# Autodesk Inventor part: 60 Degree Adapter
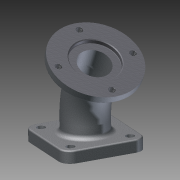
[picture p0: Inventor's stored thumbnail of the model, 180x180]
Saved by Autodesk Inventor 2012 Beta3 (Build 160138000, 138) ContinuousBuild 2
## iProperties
Created: 2010-11
Part Number: 60 Degree Adapter
Material: Default
Document SubType Name: Modeling
Designer: Beta-8540w
Density: 1 g/cm^3
Author: Beta-8540w
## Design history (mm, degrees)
sketch "Sketch1"
  geometry: L1 (50, 50)-(50, -50); L2 (50, -50)-(-50, -50); L3 (-50, -50)-(-50, 50); L4 (-50, 50)-(50, 50); C1 r 28 at (0, 0); C2 r 20 at (0, 0); 2 further points
  constraints: 8 end point, 3 coincident, 2 centre point, 1 horizontal, 9 other
  dimensions: "d0" = 100 distance of L3.end L1.start; "d8" = 8 radial gap between concentric circles of C1 C2; "d17" = 40 diameter of C2
extrude "Extrusion1" new body sketch "Sketch1" distance "d1" = 15; taper "d2" = 0 deg
sketch "Sketch2"
  geometry: L1 (0, 0)-(0, 30); L2 (-13.397, 80)-(-28.397, 105.981); A1 r 100 centre (-100, 30) between (0, 30) and (-13.397, 80)
  constraints: 4 end point, 2 point on circle, 2 tangent, 1 centre point, 1 vertical
  dimensions: "d3" = 30 distance of L1.start L1.end; "d4" = 30 distance of L2.start L2.end; "d5" = 150 deg angle of L1 L2; "d6" = 100 radius of A1
workplane "Work Plane1"
sketch "Sketch3"
  geometry: C1 r 55 at (0, 0); 2 further points
  constraints: 1 centre point, 1 coincident
  dimensions: "d9" = 110 diameter of C1
extrude "Extrusion2" join sketch "Sketch3" distance "d10" = 10; taper "d11" = 0 deg
sweep "Sweep1" dims "d12" = 0
sweep "Sweep2" dims "d13" = 0
fillet "Fillet1" dims "d14" = 14, "d15" = 6, "d16" = 2
hole "Hole1" diameter "d20" = 11; stored, may be unused: countersink angle "d24" = 90 deg, drill point angle "d26" = 118 deg; dims "d18" = 10, "d19" = 10, "d21" = 6, "d22" = 20, "d23" = 2, "d25" = 8
hole "Hole2" diameter "d29" = 11; stored, may be unused: countersink angle "d33" = 90 deg, drill point angle "d35" = 118 deg; dims "d27" = 10, "d28" = 10, "d30" = 6, "d31" = 20, "d32" = 2, "d34" = 8
hole "Hole3" diameter "d38" = 11; stored, may be unused: countersink angle "d42" = 90 deg, drill point angle "d44" = 118 deg; dims "d36" = 10, "d37" = 10, "d39" = 6, "d40" = 20, "d41" = 2, "d43" = 8
hole "Hole4" diameter "d47" = 11; stored, may be unused: countersink angle "d51" = 90 deg, drill point angle "d53" = 118 deg; dims "d45" = 10, "d46" = 10, "d48" = 6, "d49" = 20, "d50" = 2, "d52" = 8
sketch "Sketch4" dims "d54" = 90
  geometry: L1 (0, 45)-(45, 0); L2 (45, 0)-(0, -45); L3 (0, -45)-(-45, 0); L4 (-45, 0)-(0, 45); C1 r 55 at (0, 0) reference; 3 further points
  constraints: 8 end point, 2 coincident, 1 vertical alignment, 11 other
hole "Hole5" sketch "Sketch4" at (0, 45), (45, 0), (0, -45), (-45, 0) diameter "d55" = 8.376; stored, may be unused: countersink angle "d59" = 90 deg, drill point angle "d61" = 118 deg; dims "d56" = 6, "d57" = 20, "d58" = 2, "d60" = 8
sketch "Sketch5"
  geometry: C1 r 55 at (0, 0) reference; C2 r 30 at (0, 0); 1 further point
  constraints: 1 centre point, 1 coincident
  dimensions: "d62" = 60 diameter of C2
extrude "Extrusion3" cut sketch "Sketch5" distance "d63" = 6; taper "d64" = 0 deg
sketch "Sketch6"
  geometry: C1 r 20 at (0, 0) reference; C2 r 30 at (0, 0); C3 r 33 at (0, 0)
  constraints: 2 centre point, 1 coincident
  dimensions: "d65" = 60 diameter of C2; "d66" = 3 radial gap between concentric circles of C3 C2
extrude "Extrusion4" cut sketch "Sketch6" distance "d67" = 3; taper "d68" = 0 deg
fillet "Fillet2" dims "d69" = 0.5
chamfer "Chamfer1" distance "d70" = 2; stored, may be unused: second distance "d71" = 2, angle "d72" = 45 deg
chamfer "Chamfer2" distance "d73" = 1; stored, may be unused: second distance "d74" = 2, angle "d75" = 45 deg
fillet "Fillet3" dims "d76" = 0.5
body "Solid1"
